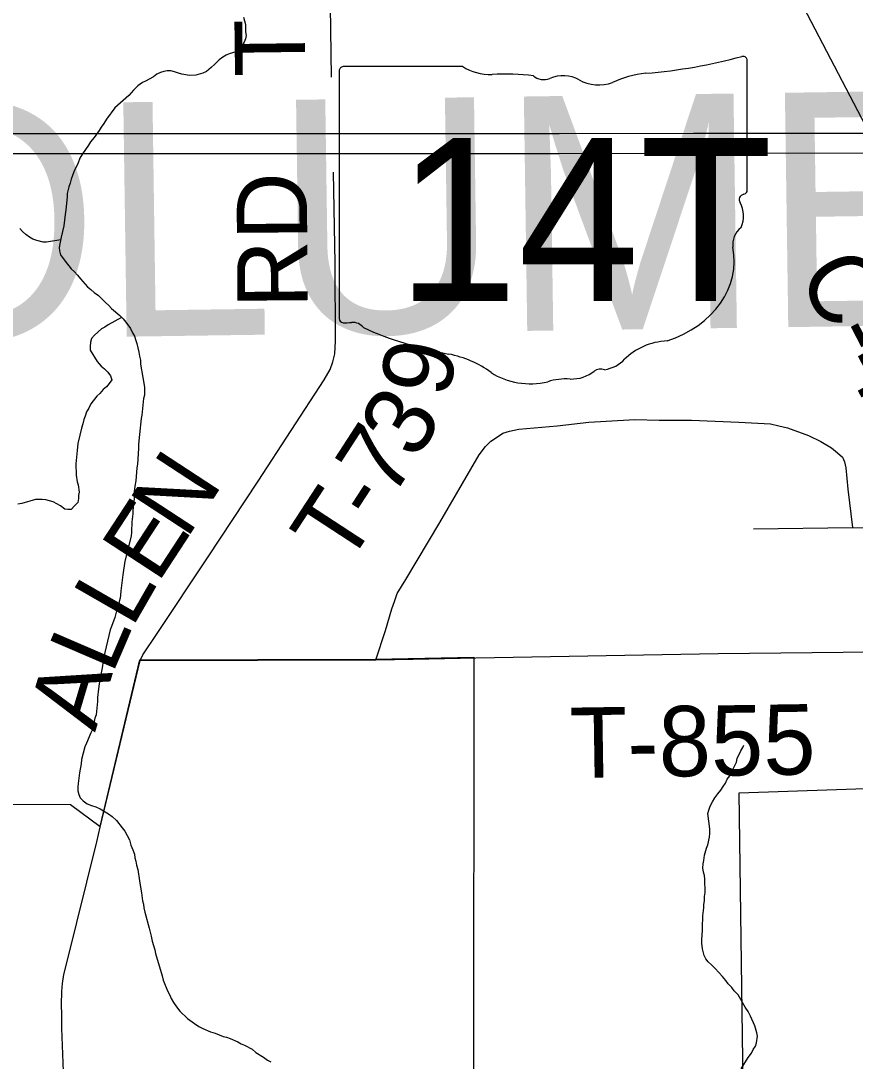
# Model space of a CAD drawing. Extents: x 0 to 34, y 0 to 22.
# Drawn here: x 3.94 to 4.614, y 18.256 to 19.097 of the extents above; entities that cross this region are included whole.
import ezdxf

# ---------------------------------------------------------------- set-up
doc = ezdxf.new("R2010")
doc.units = 0
for name, color, linetype in [('GM_X_Corporation', 7, 'Continuous'), ('GM_X_County_Road', 7, 'Continuous'), ('GM_X_County_Road_Text', 7, 'Continuous'), ('GM_X_County_Text', 7, 'Continuous'), ('GM_X_Minor_River', 7, 'Continuous'), ('GM_X_State_Location', 7, 'Continuous'), ('GM_X_State_Route', 7, 'Continuous'), ('GM_X_State_Shield', 7, 'Continuous'), ('GM_X_Township_Road', 7, 'Continuous'), ('GM_X_Township_Road_Text', 7, 'Continuous')]:
    doc.layers.add(name, color=color, linetype=linetype)

msp = doc.modelspace()

# ---------------------------------------------------------------- linework, layer by layer
at = {"layer": 'GM_X_Corporation'}
for points in [[(3.86549, 18.15956), (3.77528, 18.2852), (3.80976, 18.28505), (3.81052, 18.46465), (3.98002, 18.46392), (4.00378, 18.44598), (4.03609, 18.58076), (4.2264, 18.58127), (4.30591, 18.58279), (4.30569, 18.23481)], [(4.52352, 18.23777), (4.5203, 18.47324), (4.97669, 18.48886), (4.97487, 18.47919), (4.96611, 18.44595), (4.95544, 18.41645), (4.94578, 18.39478), (4.94304, 18.38945), (4.92922, 18.41521), (4.90296, 18.39745), (4.92425, 18.35777), (4.9112, 18.33951), (4.86382, 18.28052), (4.60039, 17.9559)]]:
    msp.add_lwpolyline(points, dxfattribs=at)
at = {"layer": 'GM_X_County_Road'}
msp.add_lwpolyline([(4.634, 18.9904), (4.62565, 19.00638), (4.49703, 19.25257)], dxfattribs=at)
at = {"layer": 'GM_X_Minor_River'}
for points in [[(4.11971, 19.09995), (4.1213, 19.09427), (4.12137, 19.08818), (4.12178, 19.08515), (4.12143, 19.08248), (4.12032, 19.07981), (4.11846, 19.07675), (4.11622, 19.07406), (4.11359, 19.07213), (4.10829, 19.07054), (4.10565, 19.06937), (4.10302, 19.06782), (4.10001, 19.0655), (4.09663, 19.06204), (4.09363, 19.05935), (4.08987, 19.05626), (4.08686, 19.05471), (4.08119, 19.05312), (4.07588, 19.05305), (4.07322, 19.0534), (4.0698, 19.05412), (4.06713, 19.05485), (4.06409, 19.05596), (4.06104, 19.05668), (4.05801, 19.05664), (4.05536, 19.05623), (4.05271, 19.05544), (4.0497, 19.05388), (4.04706, 19.05195), (4.04066, 19.04846), (4.03802, 19.04728), (4.03425, 19.04458), (4.03088, 19.04112), (4.02713, 19.03689), (4.01587, 19.02687), (4.00915, 19.01767), (4.00691, 19.01422), (4.00467, 19.01116), (4.00319, 19.00848), (3.99908, 19.00273), (3.99609, 18.99927), (3.9946, 18.99659), (3.98975, 18.98969), (3.98751, 18.98625), (3.98604, 18.98243), (3.98271, 18.97517), (3.98051, 18.96906), (3.97978, 18.96601), (3.97868, 18.96295), (3.97722, 18.95761), (3.97725, 18.95496), (3.97624, 18.9443), (3.97552, 18.94049), (3.97449, 18.93135), (3.97232, 18.92221), (3.97197, 18.91954), (3.97124, 18.91687), (3.9709, 18.91383), (3.97093, 18.91117)], [(3.97204, 18.92007), (3.96061, 18.91827), (3.95795, 18.91824), (3.95263, 18.91969), (3.94958, 18.9208), (3.94691, 18.92228), (3.94385, 18.92453), (3.94117, 18.92678), (3.93886, 18.92941)], [(3.97093, 18.91117), (3.97172, 18.90814), (3.97558, 18.90286), (3.98058, 18.89684), (3.98326, 18.89421), (3.98557, 18.89157), (3.98788, 18.88856), (3.99364, 18.88217), (3.99632, 18.87992), (3.999, 18.87767), (4.00245, 18.87505), (4.0082, 18.86942), (4.01088, 18.86717), (4.01319, 18.86453), (4.0197, 18.85891), (4.02239, 18.85628), (4.02469, 18.85365), (4.02855, 18.84838), (4.0301, 18.84497), (4.03165, 18.84233), (4.03283, 18.83892), (4.03362, 18.83627), (4.03521, 18.82945), (4.03563, 18.82603), (4.03642, 18.823), (4.03646, 18.81958), (4.03848, 18.80896), (4.03971, 18.801), (4.03978, 18.79453), (4.03906, 18.79186), (4.03769, 18.77854), (4.03696, 18.77588), (4.0356, 18.76294), (4.03493, 18.75495), (4.03497, 18.75153), (4.03398, 18.73897), (4.03363, 18.73593), (4.03262, 18.72527), (4.03191, 18.72108), (4.03122, 18.71423), (4.03126, 18.7112), (4.03023, 18.7013), (4.03027, 18.69864), (4.02958, 18.69217), (4.02961, 18.68951), (4.02926, 18.68685), (4.0293, 18.6838), (4.02895, 18.68076), (4.02388, 18.66056), (4.02211, 18.64951), (4.02074, 18.63657), (4.0204, 18.63315), (4.02005, 18.63048), (4.01932, 18.62782), (4.01861, 18.624), (4.0175, 18.62133), (4.01568, 18.61485), (4.01311, 18.6076), (4.012, 18.60493), (4.00766, 18.58663), (4.00621, 18.58015), (4.00588, 18.57596), (4.00302, 18.56149), (4.00268, 18.5573), (4.00162, 18.55045), (4.00166, 18.54703), (4.00065, 18.53638), (3.99954, 18.5337), (3.99919, 18.53104), (3.99809, 18.5276), (3.99775, 18.52456), (3.99626, 18.52188), (3.99295, 18.51348), (3.99146, 18.51042), (3.98893, 18.50013), (3.98859, 18.49671), (3.98715, 18.48947), (3.98612, 18.48071), (3.98577, 18.47805), (3.9858, 18.47501), (3.98659, 18.47198), (3.98776, 18.46933), (3.99007, 18.4667), (3.99351, 18.46446), (3.99694, 18.46298), (4.00037, 18.46188), (4.0038, 18.4604), (4.01067, 18.4563), (4.01373, 18.45406), (4.01718, 18.45106), (4.0218, 18.44503), (4.02372, 18.44239), (4.0276, 18.43522), (4.02878, 18.43105), (4.03034, 18.42727), (4.03152, 18.42386), (4.03194, 18.42083), (4.03273, 18.41818), (4.03314, 18.41476), (4.03432, 18.41136), (4.03556, 18.40225)], [(4.02124, 18.85741), (4.0103, 18.85158), (4.00767, 18.84965), (4.00503, 18.84809), (3.9994, 18.84309), (3.99678, 18.8404), (3.99605, 18.83735), (3.99571, 18.83392), (3.99575, 18.83088), (4.00154, 18.82183), (4.00462, 18.81806), (4.0073, 18.81582), (4.00998, 18.81318), (4.0123, 18.81017), (4.01347, 18.80714), (4.01123, 18.80408), (4.00898, 18.80139), (4.00635, 18.79908), (4.00373, 18.79601), (4.00111, 18.7937), (3.99625, 18.78756), (3.99477, 18.78412), (3.99291, 18.78106), (3.99181, 18.77762), (3.9907, 18.77495), (3.98998, 18.77152), (3.98888, 18.76808), (3.98743, 18.76237), (3.98599, 18.75551), (3.9853, 18.7498), (3.98429, 18.73914), (3.98439, 18.73002), (3.98521, 18.72471), (3.986, 18.72206), (3.98682, 18.71637), (3.98648, 18.7137), (3.98651, 18.71104), (3.98578, 18.70799), (3.98316, 18.7053), (3.98054, 18.70223), (3.97788, 18.7022), (3.97523, 18.70255), (3.97178, 18.70517), (3.96605, 18.70852), (3.95997, 18.70997), (3.95693, 18.71031), (3.95162, 18.71025), (3.94066, 18.70708), (3.93725, 18.70666)], [(4.51945, 18.30994), (4.51637, 18.31332), (4.51445, 18.31596), (4.51138, 18.31896), (4.50945, 18.3216), (4.50676, 18.32499), (4.501, 18.33138), (4.49831, 18.33401), (4.49525, 18.33663), (4.49332, 18.33927), (4.49215, 18.34192), (4.49057, 18.34722), (4.49014, 18.35177), (4.49011, 18.35481), (4.49078, 18.36204), (4.49072, 18.36736), (4.49106, 18.37079), (4.49103, 18.37383), (4.49171, 18.3803), (4.49168, 18.38296), (4.49241, 18.386), (4.49237, 18.38943), (4.49271, 18.39285), (4.49258, 18.40349), (4.49217, 18.40653), (4.49138, 18.40918), (4.49096, 18.41259), (4.4913, 18.41602), (4.49165, 18.41868), (4.49236, 18.42287), (4.49381, 18.42859), (4.49492, 18.43126), (4.49637, 18.43736), (4.49671, 18.44078), (4.49667, 18.44421), (4.49501, 18.45673), (4.49574, 18.4594), (4.49684, 18.46245), (4.4987, 18.46589), (4.50055, 18.46934), (4.50317, 18.47241), (4.50541, 18.47547), (4.50727, 18.47854), (4.50914, 18.48122), (4.51062, 18.48428), (4.51287, 18.48696), (4.51546, 18.4927), (4.51694, 18.49537), (4.51805, 18.49805), (4.51877, 18.5011), (4.52174, 18.50721), (4.52323, 18.50989), (4.52396, 18.5118)], [(4.03556, 18.40225), (4.03678, 18.39542), (4.03719, 18.39239), (4.03803, 18.38593), (4.03881, 18.38328), (4.03923, 18.38025), (4.04003, 18.37684), (4.04359, 18.36396), (4.04518, 18.35752), (4.04598, 18.35334), (4.04796, 18.34653), (4.04875, 18.3435), (4.05389, 18.32532), (4.05469, 18.3219), (4.0582, 18.3132), (4.06014, 18.30981), (4.0613, 18.30716), (4.06324, 18.30376), (4.06556, 18.30037), (4.06825, 18.29698), (4.07439, 18.29097), (4.08012, 18.28686), (4.08356, 18.28462), (4.087, 18.28276), (4.09309, 18.28017), (4.0969, 18.27908), (4.10338, 18.2765), (4.10604, 18.27577), (4.10909, 18.27466), (4.11519, 18.27207), (4.11786, 18.27059), (4.12053, 18.26948), (4.12663, 18.26613), (4.1297, 18.2635), (4.13581, 18.25978), (4.13925, 18.25716), (4.14192, 18.25605)], [(4.52203, 18.2503), (4.52761, 18.25948), (4.53023, 18.26294), (4.53171, 18.266), (4.53357, 18.26868), (4.5343, 18.27135), (4.535, 18.27668), (4.53459, 18.27933), (4.53301, 18.28501), (4.5295, 18.29295), (4.52756, 18.29673), (4.52525, 18.30012), (4.51945, 18.30994)]]:
    msp.add_lwpolyline(points, dxfattribs=at)
at = {"layer": 'GM_X_State_Route'}
for points in [[(3.44348, 19.00565), (3.65532, 19.00565), (3.88452, 19.00608), (4.15956, 19.00608), (4.37472, 19.00608), (4.48329, 19.0063), (4.62565, 19.00638), (4.83602, 19.00767), (4.99518, 19.00692), (5.18723, 19.00792)], [(4.31688, 18.98982), (4.37492, 18.98982), (4.48349, 18.99004), (4.634, 18.9904), (4.7889, 18.99033), (4.83683, 18.99091), (4.99561, 18.99114), (5.14989, 18.99113)], [(3.44368, 18.98938), (3.65552, 18.98938), (3.88472, 18.98982), (4.15976, 18.98982), (4.31688, 18.98982)]]:
    msp.add_lwpolyline(points, dxfattribs=at)
at = {"layer": 'GM_X_State_Shield'}
for p, q in [((4.29693, 19.06008), (4.2004, 19.06008)), ((4.52674, 18.96035), (4.52674, 19.06504)), ((4.19716, 19.05663), (4.19716, 18.85651)), ((4.52671, 18.96038), (4.52674, 18.96035))]:
    msp.add_line(p, q, dxfattribs=at)
for centre, major_axis, start_param, end_param in [((4.40934, 19.33291), (0.34952, 0), 4.814394, 5.042369), ((4.52309, 19.06547), (0.00367, 0), 6.141152, 7.989035), ((4.20094, 19.05706), (0.00382, 0), 1.712693, 3.28349), ((4.31991, 19.08331), (0.03703, 0), 4.042523, 4.731795), ((4.33219, 18.94773), (0.13295, 0), 1.404758, 1.657858), ((4.36237, 19.0581), (0.01068, 0), 3.836095, 5.185415), ((4.37806, 19.03497), (0.02221, 0), 0.950623, 2.079405), ((4.45392, 18.99895), (0.07032, 0), 1.699011, 2.107814), ((4.40673, 19.06669), (0.02672, 0), 4.081561, 5.145723), ((4.52283, 18.95995), (0.00393, 0), 5.05454, 6.418171), ((4.5259, 18.95266), (0.00568, 0), 1.883978, 3.671073), ((4.48977, 18.93943), (0.03409, 0), 5.934695, 6.695948), ((4.53989, 18.91654), (0.0248, 0), 2.387724, 3.262537), ((4.42892, 18.90322), (0.08742, 0), 5.101752, 6.440018), ((4.20097, 18.85607), (0.00385, 0), 3.00124, 4.508301), ((4.20155, 18.87655), (0.0294, 0), 4.665946, 4.897461), ((4.20757, 18.84497), (0.0106, 0), 0.519207, 1.627899), ((4.34139, 19.02477), (0.2524, 0), 4.195997, 4.488961), ((4.46578, 18.80033), (0.04788, 0), 1.647645, 2.488434), ((4.26614, 18.76661), (0.07897, 0), 0.823519, 1.323587), ((4.40512, 18.83712), (0.02824, 0), 4.937069, 5.64225), ((4.40832, 18.80961), (0.00752, 0), 1.147584, 2.315152), ((4.35156, 18.84397), (0.05011, 0), 4.026481, 4.996735), ((4.38051, 18.77478), (0.04118, 0), 1.495662, 1.94098), ((4.38417, 18.82899), (0.0267, 0), 4.691044, 5.507374)]:
    msp.add_ellipse(centre, major_axis=major_axis, ratio=0.8, start_param=start_param, end_param=end_param, dxfattribs=at)
at = {"layer": 'GM_X_Township_Road'}
msp.add_line((4.2569, 18.5813), (4.30739, 18.58227), dxfattribs=at)
for points in [[(4.19079, 19.05154), (4.18937, 19.16646), (4.19746, 19.24656)], [(4.03629, 18.58021), (4.03849, 18.5848), (4.04994, 18.60207), (4.09057, 18.66307), (4.13156, 18.72524), (4.185, 18.80704), (4.18971, 18.81548), (4.19205, 18.82149), (4.19346, 18.82797), (4.19404, 18.83823), (4.19376, 18.90122), (4.19254, 18.97483)], [(4.2266, 18.58072), (4.23446, 18.6045), (4.23952, 18.62191), (4.24166, 18.62796), (4.24388, 18.63448), (4.25087, 18.64581), (4.27834, 18.69182), (4.31019, 18.74629), (4.31526, 18.75302), (4.3197, 18.75758), (4.3249, 18.76091), (4.32943, 18.764), (4.3347, 18.76564), (4.34216, 18.76723), (4.37335, 18.76997), (4.3989, 18.77278), (4.41283, 18.77357), (4.43597, 18.77496), (4.45569, 18.77445), (4.48175, 18.77434), (4.52017, 18.77286), (4.54575, 18.77154), (4.5524, 18.76975), (4.5594, 18.7682), (4.57642, 18.76214), (4.58637, 18.75716), (4.59503, 18.75194), (4.5998, 18.74798), (4.60369, 18.74454), (4.60531, 18.74063), (4.60653, 18.736), (4.60808, 18.71873), (4.61201, 18.68759)], [(4.53176, 18.68672), (4.61201, 18.68759), (4.65124, 18.68731), (4.65243, 18.68748), (4.6535, 18.68776), (4.6557, 18.68925), (4.65742, 18.69087), (4.67041, 18.70454), (4.67686, 18.70997), (4.68297, 18.71485), (4.68941, 18.71934), (4.69474, 18.72267), (4.70322, 18.72693), (4.71176, 18.73009), (4.72073, 18.73276), (4.73014, 18.73482), (4.73815, 18.73593), (4.74481, 18.73633), (4.75174, 18.73648), (4.76488, 18.73695)], [(4.30739, 18.58227), (4.50331, 18.58601), (4.68044, 18.58779), (4.84142, 18.5993)], [(4.00108, 18.43369), (4.00398, 18.44543), (4.03629, 18.58021)], [(4.03629, 18.58021), (4.2266, 18.58072), (4.2569, 18.5813)], [(3.97169, 18.04328), (3.97342, 18.04912), (3.9773, 18.06709), (3.97845, 18.07374), (3.97905, 18.08061), (3.97907, 18.0938), (3.97792, 18.13469), (3.97573, 18.213), (3.97306, 18.28316), (3.97288, 18.29378), (3.97274, 18.30213), (3.97295, 18.31276), (3.97352, 18.31916), (3.97465, 18.32658), (3.97698, 18.33587), (4.00108, 18.43369)]]:
    msp.add_lwpolyline(points, dxfattribs=at)

# ---------------------------------------------------------------- texts
at = {"layer": 'GM_X_County_Road_Text'}
msp.add_text('C-409', height=0.056818, rotation=297.42613, dxfattribs=at).set_placement((4.5671, 18.8929))
at = {"layer": 'GM_X_County_Text'}
msp.add_text('COLUMBIANA COUNTY', height=0.1893939, rotation=0.82535, dxfattribs=at).set_placement((3.6247, 18.83612))
at = {"layer": 'GM_X_State_Location'}
for s, p in [('s', (4.35825, 18.94327)), ('r', (4.35824, 18.94327))]:
    msp.add_text(s, height=0.000189, dxfattribs=at).set_placement(p)
msp.add_text('14T', height=0.000189, rotation=0.00001, dxfattribs=at).set_placement((4.28889, 18.92949))
at = {"layer": 'GM_X_State_Shield'}
msp.add_text('14T', height=0.131836, dxfattribs=at).set_placement((4.24354, 18.87062))
at = {"layer": 'GM_X_Township_Road_Text'}
for s, height, rotation, p in [('T', 0.05682, 90.7095, (4.16975, 19.05236)), ('RD', 0.056818, 90.47768, (4.17175, 18.86516)), ('9', 0.05682, 79.21059, (4.28514, 18.79126)), ('3', 0.05682, 59.04338, (4.25941, 18.74098)), ('7', 0.05682, 57.03265, (4.23921, 18.70976)), ('N', 0.05682, 56.82088, (4.07351, 18.6773)), ('T', 0.05682, 56.86977, (4.20315, 18.65448)), ('-', 0.05682, 56.91065, (4.2264, 18.6901)), ('E', 0.05682, 56.82088, (4.05026, 18.64173)), ('L', 0.05682, 60.11878, (4.02953, 18.60561)), ('L', 0.05682, 66.7146, (4.01351, 18.56812)), ('A', 0.05682, 73.31041, (3.99973, 18.52185)), ('T-855', 0.056818, 0.87796, (4.38387, 18.48528))]:
    msp.add_text(s, height=height, rotation=rotation, dxfattribs=at).set_placement(p)

doc.saveas('drawing.dxf')
